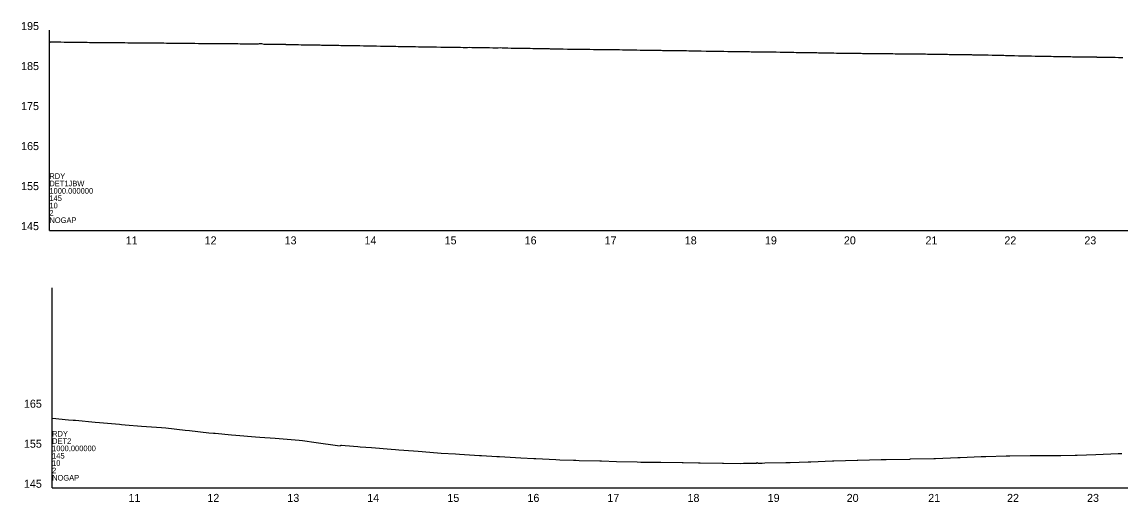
# Model space of a CAD drawing. Extents: x 573468 to 580768, y -57414 to -51768.
# Drawn here: x 573570 to 574941, y -56183 to -55583 of the extents above; entities that cross this region are included whole.
import ezdxf

# ---------------------------------------------------------------- set-up
doc = ezdxf.new("R2010")
doc.units = 0
for name, color, linetype in [('Exist Profile Cell', 7, 'Continuous'), ('Exist Vertical Profile Ground Line', 7, 'Continuous'), ('Exist Vertical Profile Horizontal Axis Label Major', 7, 'Continuous'), ('Exist Vertical Profile Vertical Axis Label', 7, 'Continuous')]:
    doc.layers.add(name, color=color, linetype=linetype)

msp = doc.modelspace()

# ---------------------------------------------------------------- linework, layer by layer
at = {"layer": 'Exist Profile Cell'}
for p, q in [((573604.3, -55843.8), (573604.3, -55593.8)), ((573604.3, -55843.8), (576243.2, -55843.8)), ((573604.3, -55843.8), (573604.3, -55843.8)), ((573607.7, -56165.6), (573607.7, -55915.6)), ((573607.7, -56165.6), (576329.7, -56165.6)), ((573607.7, -56165.6), (573607.7, -56165.6))]:
    msp.add_line(p, q, dxfattribs=at)
at = {"layer": 'Exist Vertical Profile Ground Line'}
for points in [[(573604.7, -55609.1), (573605.1, -55608.5), (573605.8, -55608.3), (573606.1, -55608.2), (573606.5, -55608.2), (573609.2, -55608.2), (573611.9, -55608.3), (573613, -55608.3), (573615.7, -55608.4), (573617.3, -55608.4), (573618.5, -55608.4), (573622.8, -55608.5), (573627.8, -55608.5), (573628.2, -55608.5), (573628.7, -55608.5), (573632.1, -55608.6), (573633.6, -55608.6), (573636, -55608.7), (573639, -55608.7), (573639.8, -55608.7), (573641.7, -55608.7), (573643.6, -55608.8), (573644.4, -55608.8), (573647.4, -55608.8), (573649.8, -55608.8), (573651.3, -55608.8), (573654.6, -55608.9), (573655.3, -55608.9), (573655.7, -55608.9), (573660.7, -55609), (573665, -55609), (573666.1, -55609), (573667.6, -55609), (573671.5, -55609), (573674.3, -55609.1), (573676.9, -55609.1), (573678, -55609.1), (573680.6, -55609.1), (573682.4, -55609.1), (573683.6, -55609.1), (573687.8, -55609.1), (573693.5, -55609.2), (573698.6, -55609.2), (573702.3, -55609.3), (573704, -55609.3), (573704.8, -55609.3), (573706.5, -55609.3), (573708.6, -55609.3), (573709.5, -55609.3), (573711.6, -55609.3), (573714.9, -55609.4), (573716.2, -55609.4), (573719.5, -55609.4), (573720.3, -55609.4), (573723.9, -55609.4), (573725.7, -55609.5), (573727.7, -55609.5), (573731.1, -55609.5), (573732.5, -55609.5), (573736.5, -55609.5), (573739.2, -55609.5), (573742, -55609.6), (573745.4, -55609.6), (573747.4, -55609.6), (573750.6, -55609.7), (573752.8, -55609.7), (573754.5, -55609.7), (573758.4, -55609.8), (573763.6, -55609.9), (573767.4, -55609.9), (573769.1, -55610), (573771.4, -55610), (573773.6, -55610), (573774.5, -55610), (573776.7, -55610), (573779.9, -55610), (573781.2, -55610), (573784.4, -55610), (573785.3, -55610), (573786, -55610), (573790.7, -55610.1), (573795.3, -55610.1), (573796.1, -55610.1), (573797.3, -55610.2), (573800.3, -55610.2), (573801.6, -55610.2), (573804.6, -55610.2), (573807, -55610.2), (573808, -55610.2), (573810.3, -55610.2), (573811.9, -55610.2), (573812.4, -55610.2), (573813.9, -55610.3), (573817.8, -55610.4), (573819.4, -55610.3), (573823.3, -55610.4), (573827.1, -55610.5), (573828.7, -55610.5), (573832.5, -55610.5), (573834.1, -55610.5), (573836.3, -55610.5), (573839.5, -55610.5), (573842.4, -55610.6), (573844.9, -55610.6), (573846.2, -55610.6), (573849.2, -55610.7), (573850.3, -55610.7), (573853.8, -55610.7), (573855.8, -55610.8), (573857.7, -55610.8), (573861.2, -55610.8), (573862.2, -55610.9), (573865.3, -55610.9), (573866.6, -55610.5), (573869.1, -55610.3), (573872, -55611), (573872.9, -55611), (573875.2, -55611), (573877.4, -55611), (573880.6, -55611.1), (573882.8, -55611.1), (573884.4, -55611.1), (573888.3, -55611.2), (573892.1, -55611.2), (573893.7, -55611.3), (573895.9, -55611.1), (573899.1, -55611.3), (573899.7, -55611.4), (573901.1, -55611.4), (573903.5, -55611.5), (573904.5, -55611.5), (573907, -55611.5), (573909.9, -55611.6), (573911.2, -55611.6), (573914.1, -55611.7), (573915.4, -55611.7), (573918.8, -55611.8), (573920.8, -55611.8), (573925.6, -55611.9), (573926.2, -55611.9), (573927.1, -55611.9), (573931.6, -55612), (573934.9, -55612), (573937, -55612.1), (573940.1, -55612.1), (573941.7, -55612.1), (573942.5, -55612.1), (573944.2, -55612.2), (573947.9, -55612.2), (573953.3, -55612.3), (573957, -55612.4), (573958.7, -55612.4), (573960.9, -55612.4), (573964.1, -55612.5), (573966, -55612.5), (573968.5, -55612.6), (573969.5, -55612.6), (573972.1, -55612.6), (573975, -55612.7), (573976.1, -55612.7), (573979, -55612.7), (573980.4, -55612.8), (573981.4, -55612.8), (573985.8, -55612.9), (573990.7, -55612.9), (573991.2, -55613), (573991.9, -55613), (573996.6, -55613.1), (573999.1, -55613.1), (574002.1, -55613.2), (574002.9, -55613.2), (574004.9, -55613.3), (574006.7, -55613.3), (574007.5, -55613.3), (574010.5, -55613.4), (574012.9, -55613.4), (574017.9, -55613.5), (574018.3, -55613.5), (574022, -55613.6), (574023.7, -55613.6), (574025.8, -55613.6), (574029.1, -55613.7), (574030.9, -55613.7), (574034.6, -55613.8), (574037.2, -55613.8), (574040, -55613.9), (574041.1, -55613.9), (574043.8, -55613.9), (574045.4, -55613.9), (574046.5, -55613.9), (574050.8, -55614), (574052.6, -55614.1), (574056.2, -55614.1), (574056.8, -55614.1), (574061.7, -55614.2), (574065.1, -55614.3), (574067.1, -55614.3), (574069.8, -55614.3), (574072.5, -55614.4), (574074.4, -55614.4), (574077.9, -55614.4), (574082.8, -55614.5), (574083.3, -55614.5), (574087, -55614.6), (574087.9, -55614.6), (574093, -55614.7), (574094.4, -55614.7), (574095.7, -55614.7), (574099.6, -55614.7), (574102.3, -55614.7), (574105, -55614.7), (574106.1, -55614.7), (574108.7, -55614.8), (574110.4, -55614.8), (574111.7, -55614.8), (574115.8, -55614.9), (574117.6, -55614.9), (574121.3, -55615.1), (574121.7, -55615.1), (574125.2, -55615.1), (574126.7, -55615.1), (574129, -55615), (574132.1, -55615.1), (574132.9, -55615.1), (574134.7, -55615.2), (574136.7, -55615.2), (574137.5, -55615.2), (574139.6, -55615.3), (574142.9, -55615.3), (574144.3, -55615.4), (574147.6, -55615.4), (574148.4, -55615.4), (574148.9, -55615.4), (574153.8, -55615.5), (574158.2, -55615.6), (574159.2, -55615.6), (574159.5, -55615.6), (574160.6, -55615.6), (574164.6, -55615.7), (574167.3, -55615.5), (574170, -55615.7), (574173.6, -55615.9), (574175.4, -55615.9), (574176.8, -55615.9), (574180.9, -55616), (574186.6, -55616), (574191.7, -55616.1), (574194, -55616.1), (574197.1, -55616.2), (574199.5, -55616.2), (574202.5, -55616.3), (574204.7, -55616.3), (574208, -55616.4), (574212.5, -55616.4), (574213.4, -55616.4), (574216.9, -55616.5), (574218.8, -55616.5), (574220.8, -55616.6), (574224.2, -55616.6), (574225.5, -55616.7), (574228.4, -55616.7), (574229.6, -55616.8), (574232.6, -55616.8), (574235.1, -55616.8), (574236.1, -55616.9), (574238.5, -55616.9), (574240.5, -55617), (574241.9, -55617), (574245.9, -55617.1), (574251.4, -55617.2), (574255.2, -55617.2), (574256.7, -55617.2), (574259, -55617.3), (574262.1, -55617.3), (574262.8, -55617.4), (574264.4, -55617.4), (574266.6, -55617.4), (574267.6, -55617.4), (574269.8, -55617.4), (574273, -55617.5), (574274.3, -55617.5), (574277.4, -55617.5), (574278.4, -55617.5), (574279.1, -55617.5), (574283.8, -55617.6), (574288.4, -55617.6), (574289.2, -55617.6), (574289.6, -55617.6), (574290.3, -55617.6), (574293.4, -55617.7), (574294.7, -55617.7), (574297.2, -55617.7), (574300.1, -55617.8), (574301, -55617.8), (574303.3, -55617.8), (574305.5, -55617.8), (574307.1, -55617.9), (574310.9, -55617.9), (574316.3, -55618), (574320.1, -55618.1), (574321.7, -55618.2), (574324, -55618.2), (574327.2, -55618.3), (574327.8, -55618.3), (574329.3, -55618.3), (574332.6, -55618.4), (574335.4, -55618.4), (574338, -55618.4), (574342.2, -55618.5), (574343.4, -55618.5), (574346.9, -55618.5), (574348.8, -55618.6), (574350.7, -55618.6), (574354.3, -55618.6), (574354.9, -55618.6), (574355.2, -55618.6), (574359.7, -55618.7), (574362.9, -55618.7), (574365.1, -55618.6), (574368.2, -55618.8), (574370, -55618.9), (574370.5, -55618.9), (574372.2, -55618.9), (574375.9, -55619), (574377.5, -55618.9), (574381.5, -55619), (574386.8, -55618.9), (574388.9, -55619.1), (574392.2, -55619.1), (574392.8, -55619.2), (574394.1, -55619.2), (574397.6, -55619.2), (574400.1, -55619.2), (574403, -55619.3), (574404.2, -55619.3), (574407.1, -55619.3), (574408.4, -55619.4), (574409.4, -55619.4), (574413.9, -55619.5), (574415.7, -55619.5), (574418.4, -55619.4), (574424.7, -55619.7), (574433.2, -55619.8), (574435.5, -55619.8), (574438.6, -55619.9), (574441, -55619.9), (574442.5, -55619.9), (574446, -55620), (574446.6, -55620), (574451.8, -55620.1), (574455.9, -55620.1), (574457.2, -55620.1), (574457.7, -55620.2), (574459, -55620.2), (574461.6, -55620.2), (574462.6, -55620.2), (574465.2, -55620.3), (574468.1, -55620.3), (574472, -55620.4), (574473, -55620.4), (574473.5, -55620.4), (574476.9, -55620.5), (574478.9, -55620.5), (574480.7, -55620.6), (574484.3, -55620.6), (574485, -55620.6), (574488.3, -55620.6), (574489.7, -55620.7), (574493.1, -55620.7), (574495.1, -55620.7), (574497.9, -55620.7), (574499.8, -55620.8), (574500.6, -55620.8), (574503.6, -55620.8), (574506, -55620.8), (574510.9, -55620.9), (574511.4, -55620.9), (574511.8, -55620.9), (574516.8, -55621), (574521.1, -55621.1), (574522.2, -55621.1), (574522.7, -55621.1), (574523.9, -55621.2), (574527.7, -55621.2), (574530.4, -55621.3), (574533.1, -55621.3), (574534.2, -55621.3), (574536.9, -55621.4), (574538.5, -55621.4), (574539.7, -55621.4), (574543.9, -55621.5), (574545.7, -55621.5), (574549.3, -55621.6), (574549.8, -55621.6), (574554.7, -55621.6), (574557.1, -55621.7), (574560.2, -55621.7), (574560.9, -55621.7), (574562.8, -55621.7), (574564.8, -55621.8), (574565.6, -55621.8), (574568.6, -55621.8), (574571, -55621.9), (574572.4, -55621.9), (574575.8, -55622), (574576.4, -55622), (574576.9, -55622), (574581.8, -55622.1), (574583.9, -55622.1), (574587.3, -55622.2), (574587.7, -55622.2), (574588.7, -55622.2), (574591.5, -55622.2), (574592.7, -55622.2), (574595.5, -55622.3), (574598.1, -55622.3), (574601.7, -55622.4), (574603.5, -55622.4), (574604.8, -55622.4), (574608.9, -55622.5), (574614.7, -55622.5), (574618.3, -55622.5), (574619.8, -55622.6), (574623.4, -55622.6), (574625.2, -55622.6), (574627.7, -55622.7), (574630.6, -55622.7), (574632.7, -55622.7), (574636, -55622.8), (574640.6, -55622.8), (574641.4, -55622.8), (574642, -55622.9), (574646.9, -55622.9), (574648.9, -55622.9), (574652.3, -55623), (574652.7, -55623), (574653.6, -55623), (574657.7, -55623), (574660.6, -55623.1), (574663.1, -55623.1), (574666.6, -55623.1), (574668.5, -55623.1), (574669.9, -55623.1), (574674, -55623.1), (574679.6, -55623.2), (574684.8, -55623.2), (574688.5, -55623.3), (574690.2, -55623.3), (574692.5, -55623.4), (574695.6, -55623.4), (574698.5, -55623.4), (574701, -55623.5), (574705.5, -55623.5), (574706.5, -55623.5), (574707.2, -55623.5), (574711.9, -55623.6), (574716.5, -55623.7), (574717.3, -55623.7), (574718.5, -55623.7), (574721.5, -55623.7), (574722.7, -55623.7), (574725.8, -55623.8), (574728.1, -55623.9), (574729.1, -55623.9), (574731.5, -55624), (574732.9, -55624.1), (574733.6, -55624.2), (574735.1, -55624.1), (574739, -55624.1), (574744.4, -55624.1), (574749.8, -55624.2), (574753.7, -55624.2), (574755.2, -55624.2), (574755.8, -55624.2), (574757.4, -55624.3), (574760.7, -55624.4), (574763, -55624.4), (574766.1, -55624.4), (574770.4, -55624.5), (574771.5, -55624.5), (574772.3, -55624.5), (574776.9, -55624.6), (574781.6, -55624.7), (574782.3, -55624.7), (574783.4, -55624.7), (574786.5, -55624.8), (574787.7, -55624.8), (574790.9, -55624.9), (574793.2, -55624.9), (574796.3, -55625), (574798.6, -55625.1), (574800.2, -55625.1), (574804, -55625.3), (574809.5, -55625.4), (574814.8, -55625.6), (574818.8, -55625.7), (574820.3, -55625.7), (574822.3, -55625.7), (574825.7, -55625.8), (574828.1, -55625.8), (574831.1, -55625.9), (574835.3, -55626), (574836.5, -55626), (574840, -55626.1), (574841.9, -55626.1), (574843.8, -55626.1), (574847.4, -55626.2), (574848.2, -55626.2), (574852.8, -55626.3), (574855.3, -55626.3), (574858.2, -55626.4), (574859.1, -55626.4), (574861.2, -55626.4), (574863.6, -55626.5), (574865.3, -55626.5), (574869, -55626.6), (574870.5, -55626.6), (574874.4, -55626.7), (574878.2, -55626.7), (574879.9, -55626.7), (574882, -55626.8), (574885.3, -55626.8), (574885.8, -55626.8), (574887.1, -55626.8), (574890.7, -55626.9), (574893.2, -55626.9), (574896.1, -55627), (574900.1, -55627), (574901.5, -55627), (574902.5, -55627), (574907, -55627.1), (574911.9, -55627.1), (574912.4, -55627.2), (574913.1, -55627.2), (574917.8, -55627.2), (574921.2, -55627.3), (574923.2, -55627.3), (574926.1, -55627.4), (574928.6, -55627.4), (574930.5, -55627.5), (574934, -55627.5), (574935.5, -55627.5), (574939.5, -55627.6), (574939.8, -55627.6), (574944.9, -55627.7)], [(573608.1, -56078.5), (573628, -56080.4), (573633.9, -56080.9), (573637, -56081.1), (573661.6, -56083.4), (573666.8, -56083.8), (573691.9, -56086.1), (573694.2, -56086.4), (573698.9, -56086.8), (573719.5, -56088.3), (573744.5, -56090.1), (573749.6, -56090.6), (573773.8, -56093.4), (573779.1, -56093.9), (573803.5, -56096.7), (573809.1, -56097.2), (573811.2, -56097.4), (573831.8, -56099.1), (573837.2, -56099.7), (573861.9, -56101.7), (573867, -56102.2), (573886.2, -56103.5), (573891.3, -56104), (573916.2, -56105.8), (573920.5, -56106.2), (573937.5, -56108.7), (573964.3, -56112.6), (573967.5, -56112.9), (573967.9, -56112.8), (573968.7, -56112.1), (573969.1, -56112.1), (573973.6, -56112.5), (573989.6, -56114), (573992.5, -56114.2), (574006.7, -56115.3), (574031.2, -56117.3), (574036.7, -56117.7), (574040.8, -56118), (574059.2, -56119.4), (574064.9, -56119.8), (574089.2, -56121.7), (574093.6, -56122), (574111.4, -56123.1), (574116.4, -56123.5), (574141.4, -56125.1), (574144.1, -56125.2), (574163, -56126.3), (574166.5, -56126.5), (574193.1, -56128), (574209.3, -56128.8), (574211.8, -56129), (574236.7, -56130.3), (574241.8, -56130.6), (574258.9, -56131), (574261.6, -56131.1), (574265.9, -56131.3), (574291.6, -56131.9), (574293.8, -56131.9), (574312.8, -56132.5), (574338.6, -56133.2), (574342.8, -56133.3), (574345.7, -56133.3), (574364.8, -56133.5), (574368, -56133.6), (574394.8, -56133.8), (574396, -56133.9), (574414.8, -56134.2), (574417, -56134.2), (574444.8, -56134.7), (574446.1, -56134.7), (574467.1, -56134.9), (574471.2, -56134.7), (574472.9, -56134.7), (574487.6, -56134.6), (574488.3, -56134), (574489.2, -56134.6), (574493.1, -56134.5), (574494.7, -56134.6), (574498, -56134.4), (574524.2, -56134), (574524.5, -56134), (574529.5, -56134), (574552.1, -56133), (574555.3, -56133), (574582.4, -56131.6), (574583.4, -56131.6), (574584, -56131.6), (574613.1, -56130.8), (574613.9, -56130.8), (574643.2, -56130.1), (574643.9, -56130.1), (574649.5, -56130), (574679, -56129.5), (574679.6, -56129.4), (574708.9, -56129), (574710.5, -56128.9), (574711.1, -56128.9), (574739.1, -56127.6), (574741.9, -56127.5), (574768, -56126.4), (574772.7, -56126.3)], [(574772.7, -56126.3), (574773.8, -56126.3), (574799.1, -56125.7), (574803.7, -56125.6), (574829.1, -56125), (574833.7, -56124.9), (574855.2, -56125), (574856.9, -56125), (574867.4, -56125.1), (574885.5, -56124.6), (574887.9, -56124.6), (574911.1, -56123.7), (574939.1, -56122.6), (574941.1, -56122.6), (574943.9, -56122.5)]]:
    msp.add_lwpolyline(points, dxfattribs=at)

# ---------------------------------------------------------------- texts
at = {"layer": 'Exist Profile Cell'}
for s, p in [('RDY', (573604.3, -55779.5)), ('DET1JBW', (573604.3, -55788.7)), ('1000.000000', (573604.3, -55797.9)), ('145', (573604.3, -55807.1)), ('10', (573604.3, -55816.3)), ('2', (573604.3, -55825.4)), ('NOGAP', (573604.3, -55834.6)), ('RDY', (573607.7, -56101.4)), ('DET2', (573607.7, -56110.6)), ('1000.000000', (573607.7, -56119.7)), ('145', (573607.7, -56128.9)), ('10', (573607.7, -56138.1)), ('2', (573607.7, -56147.3)), ('NOGAP', (573607.7, -56156.4))]:
    msp.add_text(s, height=7, dxfattribs=at).set_placement(p)
at = {"layer": 'Exist Vertical Profile Horizontal Axis Label Major'}
for s, p in [('11', (573699.7, -55861.3)), ('12', (573798.2, -55861.3)), ('13', (573898.1, -55861.3)), ('14', (573997.9, -55861.3)), ('15', (574098, -55861.3)), ('16', (574197.9, -55861.3)), ('17', (574297.8, -55861.3)), ('18', (574397.9, -55861.3)), ('19', (574498, -55861.3)), ('20', (574596.6, -55861.3)), ('21', (574698.5, -55861.3)), ('22', (574797, -55861.3)), ('23', (574896.9, -55861.3)), ('11', (573703.1, -56183.1)), ('12', (573801.6, -56183.1)), ('13', (573901.5, -56183.1)), ('14', (574001.3, -56183.1)), ('15', (574101.4, -56183.1)), ('16', (574201.4, -56183.1)), ('17', (574301.2, -56183.1)), ('18', (574401.3, -56183.1)), ('19', (574501.4, -56183.1)), ('20', (574600.1, -56183.1)), ('21', (574701.9, -56183.1)), ('22', (574800.4, -56183.1)), ('23', (574900.3, -56183.1))]:
    msp.add_text(s, height=10, dxfattribs=at).set_placement(p)
at = {"layer": 'Exist Vertical Profile Vertical Axis Label'}
for s, p in [('195', (573569, -55593.5)), ('185', (573569, -55643.5)), ('175', (573569, -55693.5)), ('165', (573569, -55743.5)), ('155', (573569, -55793.5)), ('145', (573569, -55843.5)), ('165', (573572.5, -56065.4)), ('155', (573572.5, -56115.4)), ('145', (573572.5, -56165.4))]:
    msp.add_text(s, height=10, dxfattribs=at).set_placement(p)

doc.saveas('drawing.dxf')
